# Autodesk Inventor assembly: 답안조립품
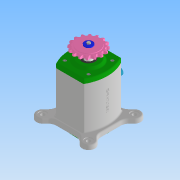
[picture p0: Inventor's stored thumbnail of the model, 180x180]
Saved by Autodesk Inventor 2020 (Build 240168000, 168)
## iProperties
Created: 2022-01
Part Number: 답안조립품
Document SubType Name: Assembly
Designer: user
Author: user
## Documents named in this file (13)
- C:\Users\user\Desktop\720117V1015\답안조립품.iam
- C:\Users\user\Desktop\720117V1015\베어링 6203.ipt
- C:\Users\user\Desktop\720117V1015\본체.ipt
- C:\Users\user\Desktop\720117V1015\볼트 M4 x 12.ipt
- C:\Users\user\Desktop\720117V1015\부시.ipt
- C:\Users\user\Desktop\720117V1015\스프로킷.ipt
- C:\Users\user\Desktop\720117V1015\슬라이더.ipt
- C:\Users\user\Desktop\720117V1015\오일 실 17 x 30 x 8.ipt
- C:\Users\user\Desktop\720117V1015\와셔 4 x 20.ipt
- C:\Users\user\Desktop\720117V1015\육각머리볼트 M4.ipt
- C:\Users\user\Desktop\720117V1015\커버.ipt
- C:\Users\user\Desktop\720117V1015\키 5 x 5.ipt
- C:\Users\user\Desktop\720117V1015\편심축.ipt
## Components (8 placed, 1 different names)
1. M4x0.7x12:1
2. M4x0.7x12:3
3. M4x0.7x12:4
4. M4x0.7x12:5
5. M4x0.7x12:2
6. M4x0.7x12:6
7. M4x0.7x12:7
8. M4x0.7x12:8
